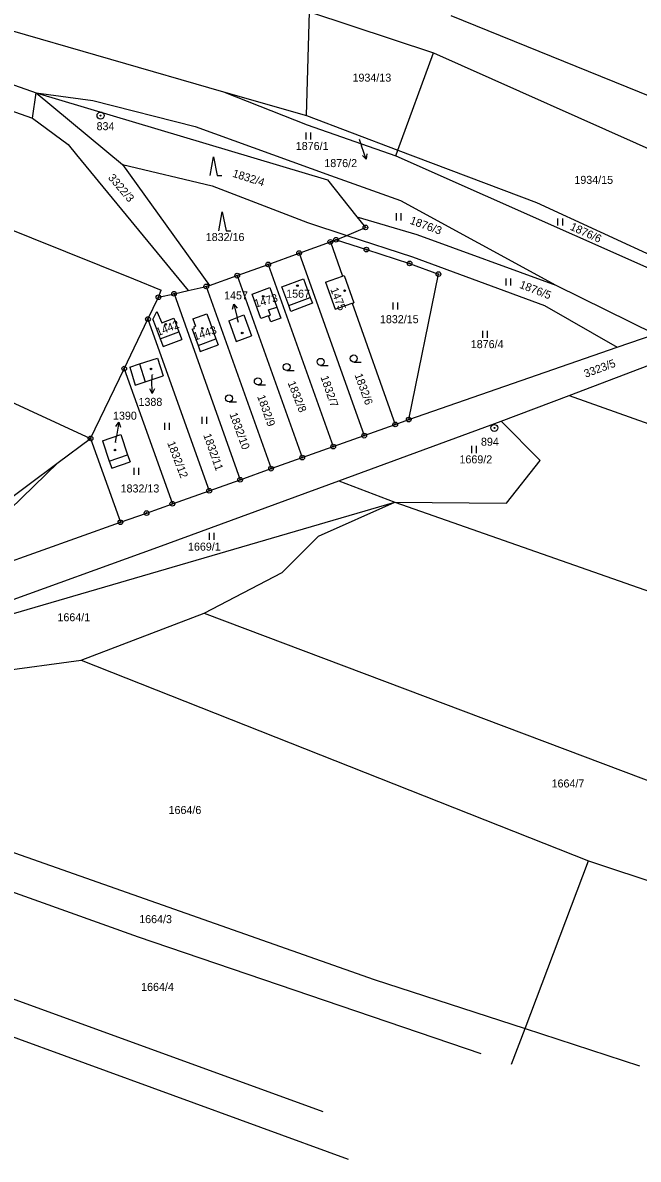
# Model space of a CAD drawing. Extents: x -763205 to -760228, y -1155311 to -1152844.
# Drawn here: x -761496.9 to -761366.2, y -1155176.6 to -1154935.1 of the extents above; entities that cross this region are included whole.
import ezdxf

# ---------------------------------------------------------------- set-up
doc = ezdxf.new("R2010")
doc.units = 0
for name, color, linetype in [('Vrstva 1', 7, 'Continuous'), ('Vrstva 16', 7, 'Continuous'), ('Vrstva 17', 7, 'Continuous'), ('Vrstva 18', 7, 'Continuous'), ('Vrstva 19', 7, 'Continuous'), ('Vrstva 24', 7, 'Continuous'), ('Vrstva 25', 7, 'Continuous'), ('Vrstva 4', 7, 'Continuous'), ('Vrstva 6', 7, 'Continuous')]:
    doc.layers.add(name, color=color, linetype=linetype)

msp = doc.modelspace()

# ---------------------------------------------------------------- linework, layer by layer
at = {"layer": 'Vrstva 1'}
for p, q in [((-761551.57, -1154921.74), (-761454.31, -1154949.76)), ((-761558.05, -1154927.37), (-761494.1, -1154950.01)), ((-761555.49, -1154933.97), (-761494.82, -1154955.41)), ((-761436.68, -1154954.84), (-761436, -1154932.78)), ((-761494.82, -1154955.41), (-761494.1, -1154950.01)), ((-761494.1, -1154950.01), (-761475.77, -1154965.23)), ((-761494.1, -1154950.01), (-761432.22, -1154968.52)), ((-761454.31, -1154949.76), (-761436.68, -1154954.84)), ((-761494.82, -1154955.41), (-761487.29, -1154961)), ((-761436.68, -1154954.84), (-761417.28, -1154962.18)), ((-761487.29, -1154961), (-761485.48, -1154963.21)), ((-761417.28, -1154962.18), (-761387.81, -1154973.33)), ((-761485.48, -1154963.21), (-761461.81, -1154992.01)), ((-761475.77, -1154965.23), (-761457.29, -1154990.91)), ((-761432.22, -1154968.52), (-761425.95, -1154976.37)), ((-761387.81, -1154973.33), (-761350.06, -1154990.75)), ((-761425.95, -1154976.37), (-761424.16, -1154978.61)), ((-761428.14, -1154980.28), (-761424.16, -1154978.61)), ((-761438.23, -1154984.05), (-761431.61, -1154981.67)), ((-761431.61, -1154981.67), (-761430.4, -1154981.23)), ((-761431.61, -1154981.67), (-761429.02, -1154988.94)), ((-761430.4, -1154981.23), (-761428.14, -1154980.28)), ((-761430.4, -1154981.23), (-761423.96, -1154983.31)), ((-761444.8, -1154986.45), (-761438.23, -1154984.05)), ((-761438.23, -1154984.05), (-761424.41, -1155022.83)), ((-761423.96, -1154983.31), (-761414.77, -1154986.24)), ((-761451.38, -1154988.84), (-761444.8, -1154986.45)), ((-761444.8, -1154986.45), (-761431, -1155025.16)), ((-761414.77, -1154986.24), (-761408.65, -1154988.52)), ((-761457.29, -1154990.91), (-761451.38, -1154988.84)), ((-761451.38, -1154988.84), (-761437.59, -1155027.49)), ((-761441.89, -1154991.24), (-761437.34, -1154989.52)), ((-761437.34, -1154989.52), (-761435.87, -1154993.46)), ((-761432.66, -1154990.22), (-761429.02, -1154988.94)), ((-761429.02, -1154988.94), (-761428.67, -1154988.82)), ((-761428.67, -1154988.82), (-761426.64, -1154994.59)), ((-761414.97, -1155019.42), (-761408.65, -1154988.52)), ((-761461.81, -1154992.01), (-761457.96, -1154991.14)), ((-761457.96, -1154991.14), (-761457.29, -1154990.91)), ((-761457.96, -1154991.14), (-761444.2, -1155029.84)), ((-761448.23, -1154992.75), (-761444.48, -1154991.39)), ((-761444.48, -1154991.39), (-761442.97, -1154995.5)), ((-761440.42, -1154995.19), (-761441.89, -1154991.24)), ((-761432.66, -1154990.22), (-761430.61, -1154995.98)), ((-761470.33, -1154998.06), (-761468.1, -1154993.44)), ((-761468.1, -1154993.44), (-761464.79, -1154992.68)), ((-761464.79, -1154992.68), (-761461.81, -1154992.01)), ((-761464.79, -1154992.68), (-761450.76, -1155032.2)), ((-761446.36, -1154997.93), (-761448.23, -1154992.75)), ((-761435.87, -1154993.46), (-761435.38, -1154994.72)), ((-761469.32, -1154998.16), (-761468.44, -1154996.44)), ((-761468.44, -1154996.44), (-761467.41, -1154998.85)), ((-761442.97, -1154995.5), (-761442.11, -1154997.88)), ((-761439.97, -1154996.46), (-761440.42, -1154995.19)), ((-761435.38, -1154994.72), (-761439.97, -1154996.46)), ((-761430.61, -1154995.98), (-761426.97, -1154994.71)), ((-761426.97, -1154994.71), (-761426.64, -1154994.59)), ((-761426.97, -1154994.71), (-761417.82, -1155020.45)), ((-761475.36, -1155008.6), (-761470.33, -1154998.06)), ((-761470.33, -1154998.06), (-761457.34, -1155034.54)), ((-761469.32, -1154998.16), (-761468.84, -1154999.4)), ((-761467.41, -1154998.85), (-761464.87, -1154997.88)), ((-761464.87, -1154997.88), (-761463.77, -1155000.75)), ((-761460.78, -1154998.03), (-761457.8, -1154996.97)), ((-761460.78, -1154998.03), (-761460.26, -1154999.57)), ((-761457.8, -1154996.97), (-761457.13, -1154998.85)), ((-761457.13, -1154998.85), (-761455.9, -1155002.29)), ((-761453.18, -1154998.41), (-761449.98, -1154997.18)), ((-761453.18, -1154998.41), (-761451.59, -1155002.86)), ((-761449.98, -1154997.18), (-761448.37, -1155001.59)), ((-761444.74, -1154997.35), (-761446.36, -1154997.93)), ((-761444.28, -1154998.66), (-761444.74, -1154997.35)), ((-761442.11, -1154997.88), (-761444.28, -1154998.66)), ((-761468.84, -1154999.4), (-761467.73, -1155002.26)), ((-761463.77, -1155000.75), (-761463.14, -1155002.4)), ((-761460.95, -1155000.21), (-761460.5, -1155000.06)), ((-761460.95, -1155000.21), (-761459.7, -1155003.66)), ((-761460.61, -1154999.7), (-761460.26, -1154999.57)), ((-761460.61, -1154999.7), (-761460.5, -1155000.06)), ((-761451.59, -1155002.86), (-761448.37, -1155001.59)), ((-761370.7, -1155004.05), (-761362.61, -1155001.24)), ((-761467.73, -1155002.26), (-761467.1, -1155003.91)), ((-761467.1, -1155003.91), (-761463.14, -1155002.4)), ((-761459.7, -1155003.66), (-761459.23, -1155004.93)), ((-761459.23, -1155004.93), (-761455.45, -1155003.56)), ((-761455.9, -1155002.29), (-761455.45, -1155003.56)), ((-761472.16, -1155007.6), (-761468.33, -1155006.34)), ((-761468.33, -1155006.34), (-761467.09, -1155010.15)), ((-761414.97, -1155019.42), (-761370.7, -1155004.05)), ((-761380.91, -1155014.27), (-761359.34, -1155006.12)), ((-761482.52, -1155023.43), (-761475.36, -1155008.6)), ((-761475.36, -1155008.6), (-761465.16, -1155037.31)), ((-761474.22, -1155008.27), (-761472.16, -1155007.6)), ((-761474.22, -1155008.27), (-761473.02, -1155012.07)), ((-761470.95, -1155011.4), (-761467.09, -1155010.15)), ((-761473.02, -1155012.07), (-761470.95, -1155011.4)), ((-761395.34, -1155019.72), (-761380.91, -1155014.27)), ((-761429.84, -1155032.4), (-761395.34, -1155019.72)), ((-761424.41, -1155022.83), (-761417.82, -1155020.45)), ((-761417.82, -1155020.45), (-761414.97, -1155019.42)), ((-761395.34, -1155019.72), (-761387.07, -1155028.11)), ((-761480.01, -1155023.91), (-761476.13, -1155022.6)), ((-761476.13, -1155022.6), (-761474.69, -1155026.92)), ((-761431, -1155025.16), (-761424.41, -1155022.83)), ((-761489.4, -1155028.54), (-761482.52, -1155023.43)), ((-761482.52, -1155023.43), (-761476.19, -1155041.23)), ((-761480.01, -1155023.91), (-761478.59, -1155028.22)), ((-761437.59, -1155027.49), (-761431, -1155025.16)), ((-761474.69, -1155026.92), (-761474.11, -1155028.41)), ((-761444.2, -1155029.84), (-761437.59, -1155027.49)), ((-761394.18, -1155037.17), (-761387.07, -1155028.11)), ((-761510.7, -1155044.35), (-761489.4, -1155028.54)), ((-761502.44, -1155041.2), (-761489.4, -1155028.54)), ((-761478.59, -1155028.22), (-761478.01, -1155029.72)), ((-761478.01, -1155029.72), (-761474.11, -1155028.41)), ((-761450.76, -1155032.2), (-761444.2, -1155029.84)), ((-761468.24, -1155046.52), (-761429.84, -1155032.4)), ((-761457.34, -1155034.54), (-761450.76, -1155032.2)), ((-761465.16, -1155037.31), (-761457.34, -1155034.54)), ((-761542.95, -1155073.5), (-761417.92, -1155036.97)), ((-761470.63, -1155039.27), (-761465.16, -1155037.31)), ((-761417.92, -1155036.97), (-761394.18, -1155037.17)), ((-761417.92, -1155036.97), (-761277.43, -1155086.2)), ((-761476.19, -1155041.23), (-761470.63, -1155039.27)), ((-761519.59, -1155056.72), (-761476.19, -1155041.23)), ((-761542.95, -1155073.5), (-761468.24, -1155046.52)), ((-761390.25, -1155148.78), (-761376.78, -1155113.13)), ((-761376.78, -1155113.13), (-761292.34, -1155141.39)), ((-761393.12, -1155156.37), (-761390.25, -1155148.78))]:
    msp.add_line(p, q, dxfattribs=at)
at = {"layer": 'Vrstva 16'}
for p, q in [((-761425.47, -1154959.83), (-761424.97, -1154961.25)), ((-761423.977, -1154964.081), (-761424.97, -1154961.25)), ((-761452.128, -1154994.885), (-761451.38, -1154997.79)), ((-761451.13, -1154998.76), (-761451.38, -1154997.79)), ((-761469.5, -1155009.93), (-761469.48, -1155010.9)), ((-761469.413, -1155013.899), (-761469.48, -1155010.9)), ((-761476.527, -1155019.981), (-761477.02, -1155022.94)), ((-761477.25, -1155024.31), (-761477.02, -1155022.94))]:
    msp.add_line(p, q, dxfattribs=at)
for points in [[(-761423.836, -1154962.972), (-761423.977, -1154964.081), (-761424.78, -1154963.303)], [(-761452.363, -1154995.978), (-761452.128, -1154994.885), (-761451.394, -1154995.728)], [(-761468.935, -1155012.888), (-761469.413, -1155013.899), (-761469.935, -1155012.911)], [(-761477.184, -1155020.885), (-761476.527, -1155019.981), (-761476.198, -1155021.049)]]:
    msp.add_lwpolyline(points, dxfattribs=at)
at = {"layer": 'Vrstva 24'}
for centre, radius in [((-761480.4, -1154954.83), 0.75), ((-761480.4, -1154954.83), 0.1), ((-761424.16, -1154978.61), 0.5), ((-761424.16, -1154978.61), 0.1), ((-761431.61, -1154981.67), 0.5), ((-761431.61, -1154981.67), 0.1), ((-761430.4, -1154981.23), 0.5), ((-761430.4, -1154981.23), 0.1), ((-761438.23, -1154984.05), 0.5), ((-761438.23, -1154984.05), 0.1), ((-761423.96, -1154983.31), 0.5), ((-761423.96, -1154983.31), 0.1), ((-761444.8, -1154986.45), 0.5), ((-761444.8, -1154986.45), 0.1), ((-761414.77, -1154986.24), 0.5), ((-761414.77, -1154986.24), 0.1), ((-761451.38, -1154988.84), 0.5), ((-761451.38, -1154988.84), 0.1), ((-761408.65, -1154988.52), 0.5), ((-761408.65, -1154988.52), 0.1), ((-761457.96, -1154991.14), 0.5), ((-761457.96, -1154991.14), 0.1), ((-761468.1, -1154993.44), 0.5), ((-761468.1, -1154993.44), 0.1), ((-761464.79, -1154992.68), 0.5), ((-761464.79, -1154992.68), 0.1), ((-761470.33, -1154998.06), 0.5), ((-761470.33, -1154998.06), 0.1), ((-761475.36, -1155008.6), 0.5), ((-761475.36, -1155008.6), 0.1), ((-761417.82, -1155020.45), 0.5), ((-761417.82, -1155020.45), 0.1), ((-761414.97, -1155019.42), 0.5), ((-761414.97, -1155019.42), 0.1), ((-761396.78, -1155021.19), 0.75), ((-761482.52, -1155023.43), 0.5), ((-761482.52, -1155023.43), 0.1), ((-761424.41, -1155022.83), 0.5), ((-761424.41, -1155022.83), 0.1), ((-761396.78, -1155021.19), 0.1), ((-761431, -1155025.16), 0.5), ((-761431, -1155025.16), 0.1), ((-761437.59, -1155027.49), 0.5), ((-761437.59, -1155027.49), 0.1), ((-761444.2, -1155029.84), 0.5), ((-761444.2, -1155029.84), 0.1), ((-761450.76, -1155032.2), 0.5), ((-761450.76, -1155032.2), 0.1), ((-761457.34, -1155034.54), 0.5), ((-761457.34, -1155034.54), 0.1), ((-761465.16, -1155037.31), 0.5), ((-761465.16, -1155037.31), 0.1), ((-761470.63, -1155039.27), 0.5), ((-761470.63, -1155039.27), 0.1), ((-761476.19, -1155041.23), 0.5), ((-761476.19, -1155041.23), 0.1)]:
    msp.add_circle(centre, radius, dxfattribs=at)
at = {"layer": 'Vrstva 25'}
for p, q in [((-761436.73, -1154959.94), (-761436.73, -1154958.44)), ((-761435.73, -1154959.94), (-761435.73, -1154958.44)), ((-761417.56, -1154977.09), (-761417.56, -1154975.59)), ((-761416.56, -1154977.09), (-761416.56, -1154975.59)), ((-761383.27, -1154978.17), (-761383.27, -1154976.67)), ((-761382.27, -1154978.17), (-761382.27, -1154976.67)), ((-761394.3, -1154990.94), (-761394.3, -1154989.44)), ((-761393.3, -1154990.94), (-761393.3, -1154989.44)), ((-761418.29, -1154996.04), (-761418.29, -1154994.54)), ((-761417.29, -1154996.04), (-761417.29, -1154994.54)), ((-761399.26, -1155002.04), (-761399.26, -1155000.54)), ((-761398.26, -1155002.04), (-761398.26, -1155000.54)), ((-761433.67, -1155007.91), (-761432.07, -1155007.91)), ((-761426.64, -1155007.19), (-761425.04, -1155007.19)), ((-761440.87, -1155008.99), (-761439.27, -1155008.99)), ((-761446.99, -1155012.05), (-761445.39, -1155012.05)), ((-761453.12, -1155015.66), (-761451.52, -1155015.66)), ((-761466.76, -1155021.6), (-761466.76, -1155020.1)), ((-761465.76, -1155021.6), (-761465.76, -1155020.1)), ((-761458.84, -1155020.34), (-761458.84, -1155018.84)), ((-761457.84, -1155020.34), (-761457.84, -1155018.84)), ((-761401.59, -1155026.52), (-761401.59, -1155025.02)), ((-761400.59, -1155026.52), (-761400.59, -1155025.02)), ((-761473.25, -1155031.15), (-761473.25, -1155029.65)), ((-761472.25, -1155031.15), (-761472.25, -1155029.65)), ((-761457.26, -1155044.98), (-761457.26, -1155043.48)), ((-761456.26, -1155044.98), (-761456.26, -1155043.48))]:
    msp.add_line(p, q, dxfattribs=at)
for points in [[(-761457.15, -1154967.57), (-761456.45, -1154963.57), (-761455.65, -1154967.57), (-761454.65, -1154967.57)], [(-761455.26, -1154979.29), (-761454.56, -1154975.29), (-761453.76, -1154979.29), (-761452.76, -1154979.29)]]:
    msp.add_lwpolyline(points, dxfattribs=at)
for centre, radius in [((-761438.6, -1154990.96), 0.175), ((-761428.58, -1154992.04), 0.175), ((-761445.87, -1154993.22), 0.175), ((-761466.56, -1154999.18), 0.175), ((-761458.8, -1155000.02), 0.175), ((-761450.32, -1155001.01), 0.175), ((-761433.67, -1155007.16), 0.75), ((-761426.64, -1155006.44), 0.75), ((-761469.68, -1155008.67), 0.175), ((-761440.87, -1155008.24), 0.75), ((-761446.99, -1155011.3), 0.75), ((-761453.12, -1155014.91), 0.75), ((-761477.34, -1155025.88), 0.175)]:
    msp.add_circle(centre, radius, dxfattribs=at)
at = {"layer": 'Vrstva 4'}
for p, q in [((-761440.42, -1154995.19), (-761435.87, -1154993.46)), ((-761444.72, -1154996.12), (-761442.97, -1154995.5)), ((-761444.34, -1154997.21), (-761444.72, -1154996.12)), ((-761444.74, -1154997.35), (-761444.34, -1154997.21)), ((-761467.73, -1155002.26), (-761463.77, -1155000.75)), ((-761459.7, -1155003.66), (-761455.9, -1155002.29)), ((-761472.16, -1155007.6), (-761470.95, -1155011.4)), ((-761478.59, -1155028.22), (-761474.69, -1155026.92))]:
    msp.add_line(p, q, dxfattribs=at)
at = {"layer": 'Vrstva 6'}
for p, q in [((-761436, -1154932.78), (-761409.73, -1154941.52)), ((-761405.99, -1154933.61), (-761349.41, -1154956.53)), ((-761417.28, -1154962.18), (-761409.73, -1154941.52)), ((-761409.73, -1154941.52), (-761333.18, -1154975.68)), ((-761494.1, -1154950.01), (-761482.03, -1154951.66)), ((-761454.31, -1154949.76), (-761436.52, -1154956.78)), ((-761482.03, -1154951.66), (-761460.3, -1154957.14)), ((-761460.3, -1154957.14), (-761431.6, -1154967.58)), ((-761436.52, -1154956.78), (-761417.7, -1154963.38)), ((-761417.7, -1154963.38), (-761417.28, -1154962.18)), ((-761475.77, -1154965.23), (-761456.71, -1154969.78)), ((-761417.7, -1154963.38), (-761352.18, -1154992.53)), ((-761431.6, -1154967.58), (-761416.71, -1154972.89)), ((-761456.71, -1154969.78), (-761436.47, -1154977.58)), ((-761513.24, -1154973.56), (-761473.39, -1154989.54)), ((-761416.71, -1154972.89), (-761383.71, -1154990.87)), ((-761425.95, -1154976.37), (-761413.24, -1154980.1)), ((-761436.47, -1154977.58), (-761428.14, -1154980.28)), ((-761428.14, -1154980.28), (-761414.19, -1154984.81)), ((-761413.24, -1154980.1), (-761383.71, -1154990.87)), ((-761414.19, -1154984.81), (-761386.15, -1154995.17)), ((-761473.39, -1154989.54), (-761467.5, -1154991.9)), ((-761468.1, -1154993.44), (-761467.5, -1154991.9)), ((-761383.71, -1154990.87), (-761362.61, -1155001.24)), ((-761541.61, -1154996.23), (-761482.52, -1155023.43)), ((-761386.15, -1154995.17), (-761370.7, -1155004.05)), ((-761380.91, -1155014.27), (-761307.23, -1155040.5)), ((-761429.84, -1155032.4), (-761417.92, -1155036.97)), ((-761434.12, -1155044.17), (-761417.92, -1155036.97)), ((-761441.84, -1155051.9), (-761434.12, -1155044.17)), ((-761458.43, -1155060.54), (-761441.84, -1155051.9)), ((-761484.55, -1155070.54), (-761458.43, -1155060.54)), ((-761458.43, -1155060.54), (-761358.05, -1155098.4)), ((-761504.53, -1155073.2), (-761484.55, -1155070.54)), ((-761484.55, -1155070.54), (-761376.78, -1155113.13)), ((-761521.05, -1155103.58), (-761422.29, -1155138.39)), ((-761515.62, -1155113.84), (-761472.44, -1155129.32)), ((-761472.44, -1155129.32), (-761399.66, -1155154.07)), ((-761525.9, -1155132.65), (-761433.2, -1155166.4)), ((-761542.65, -1155134.61), (-761427.85, -1155176.55)), ((-761422.29, -1155138.39), (-761390.25, -1155148.78)), ((-761390.25, -1155148.78), (-761365.93, -1155156.67))]:
    msp.add_line(p, q, dxfattribs=at)

# ---------------------------------------------------------------- texts
at = {"layer": 'Vrstva 16'}
for s, p in [('1876/2', (-761432.887, -1154965.78)), ('1457', (-761454.167, -1154993.89)), ('1388', (-761472.347, -1155016.5)), ('1390', (-761477.757, -1155019.44))]:
    msp.add_text(s, height=1.7, dxfattribs=at).set_placement(p)
at = {"layer": 'Vrstva 17'}
for s, p in [('834', (-761481.248, -1154957.94)), ('894', (-761399.624, -1155024.97))]:
    msp.add_text(s, height=1.7, dxfattribs=at).set_placement(p)
at = {"layer": 'Vrstva 18'}
for s, height, p in [('1934/13', 1.7, (-761426.897, -1154947.62)), ('1876/1', 1.7, (-761438.947, -1154962.14)), ('1876/2', 0.1, (-761425.447, -1154959.83)), ('1934/15', 1.7, (-761379.787, -1154969.34)), ('1832/16', 1.7, (-761458.067, -1154981.49)), ('1832/15', 1.7, (-761421.077, -1154998.94)), ('1876/4', 1.7, (-761401.787, -1155004.24)), ('1669/2', 1.7, (-761404.187, -1155028.72)), ('1832/13', 1.7, (-761476.147, -1155034.9)), ('1669/1', 1.7, (-761461.837, -1155047.26)), ('1664/1', 1.7, (-761489.557, -1155062.26)), ('1664/7', 1.7, (-761384.627, -1155097.57)), ('1664/6', 1.7, (-761465.957, -1155103.2)), ('1664/3', 1.7, (-761472.197, -1155126.39)), ('1664/4', 1.7, (-761471.787, -1155140.78))]:
    msp.add_text(s, height=height, dxfattribs=at).set_placement(p)
for s, rotation, p in [('3322/3', 310.65772, (-761478.915, -1154968.1)), ('1832/4', 342.28499, (-761452.516, -1154967.799)), ('1876/3', 339.82127, (-761414.851, -1154977.775)), ('1876/6', 335.40949, (-761380.843, -1154979.023)), ('1876/5', 338.84724, (-761391.594, -1154991.392)), ('3323/5', 20.3973, (-761377.387, -1155010.537)), ('1832/7', 289.05721, (-761433.712, -1155010.391)), ('1832/6', 289.91664, (-761426.486, -1155009.939)), ('1832/8', 291.46363, (-761440.706, -1155011.605)), ('1832/9', 289.57287, (-761447.168, -1155014.5)), ('1832/10', 290.03124, (-761453.055, -1155018.249)), ('1832/11', 289.45828, (-761458.619, -1155022.7)), ('1832/12', 290.89067, (-761466.28, -1155024.367))]:
    msp.add_text(s, height=1.7, rotation=rotation, dxfattribs=at).set_placement(p)
at = {"layer": 'Vrstva 19'}
for s, height, p in [('1567', 1.7, (-761440.992, -1154993.53)), ('1457', 0.1, (-761451.107, -1154998.76)), ('1388', 0.1, (-761469.477, -1155009.93)), ('1390', 0.1, (-761477.227, -1155024.31))]:
    msp.add_text(s, height=height, dxfattribs=at).set_placement(p)
for s, rotation, p in [('1475', 291.52092, (-761431.646, -1154991.735)), ('1473', 15.75634, (-761447.494, -1154995.646)), ('1442', 21.60051, (-761468.223, -1155001.702)), ('1443', 18.44924, (-761460.4, -1155002.654))]:
    msp.add_text(s, height=1.7, rotation=rotation, dxfattribs=at).set_placement(p)

doc.saveas('drawing.dxf')
